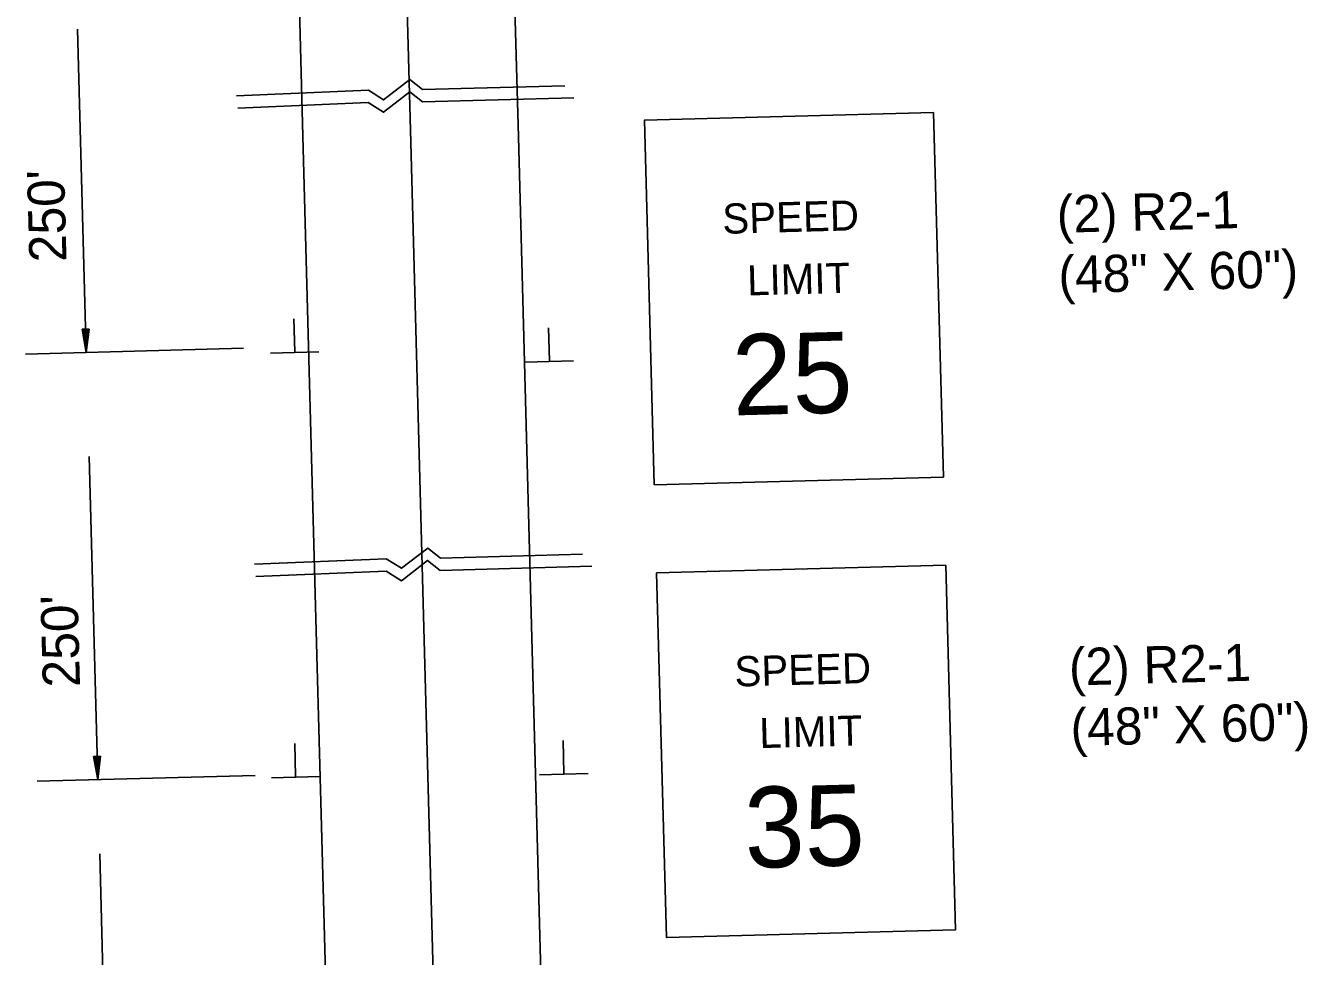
# Model space of a CAD drawing. Extents: x 1926836 to 1933254, y 596317 to 604524.
# Drawn here: x 1930973.1 to 1931180.1, y 596501.1 to 596651.4 of the extents above; entities that cross this region are included whole.
import ezdxf

# ---------------------------------------------------------------- set-up
doc = ezdxf.new("R2010")
doc.units = 0
doc.layers.add('Default', color=7, linetype='Continuous')

msp = doc.modelspace()

# ---------------------------------------------------------------- linework, layer by layer
at = {"layer": 'Default'}
for p, q in [((1931017.97, 596631.53), (1931016.3, 596693.48)), ((1931035.33, 596632.46), (1931033.69, 596693.61)), ((1931052.7, 596633.38), (1931051.08, 596693.74)), ((1930982.92, 596598.6), (1930981.52, 596650.77)), ((1931054.71, 596558.55), (1931052.7, 596633.38)), ((1931019.95, 596557.62), (1931017.97, 596631.53)), ((1931037.33, 596558.09), (1931035.33, 596632.46)), ((1931016.59, 596598.7), (1931016.45, 596604.04)), ((1930983.38, 596602.36), (1930982.26, 596602.33)), ((1930982.26, 596602.33), (1930982.92, 596598.6)), ((1930982.35, 596602.33), (1930982.9, 596599.22)), ((1930982.44, 596602.33), (1930982.88, 596599.87)), ((1930982.54, 596602.34), (1930982.87, 596600.49)), ((1930982.63, 596602.34), (1930982.85, 596601.13)), ((1930982.73, 596602.34), (1930982.83, 596601.75)), ((1930982.91, 596602.35), (1930982.83, 596601.75)), ((1930983, 596602.35), (1930982.85, 596601.13)), ((1930983.1, 596602.35), (1930982.87, 596600.49)), ((1930983.19, 596602.35), (1930982.88, 596599.87)), ((1930983.29, 596602.36), (1930982.9, 596599.22)), ((1930983.38, 596602.36), (1930982.92, 596598.6)), ((1931057.7, 596597.23), (1931057.56, 596602.57)), ((1930973.13, 596598.33), (1931008.33, 596599.28)), ((1931020.48, 596598.69), (1931012.66, 596598.48)), ((1931061.59, 596597.22), (1931053.77, 596597.01)), ((1930984.77, 596529.62), (1930983.37, 596581.79)), ((1931056.56, 596489.57), (1931054.71, 596558.55)), ((1931021.8, 596488.64), (1931019.95, 596557.62)), ((1931039.18, 596489.11), (1931037.33, 596558.09)), ((1931060.05, 596530.6), (1931059.91, 596535.94)), ((1931016.73, 596530.12), (1931016.59, 596535.45)), ((1930985.23, 596533.38), (1930984.11, 596533.35)), ((1930984.11, 596533.35), (1930984.77, 596529.62)), ((1930984.2, 596533.35), (1930984.75, 596530.24)), ((1930984.3, 596533.35), (1930984.74, 596530.89)), ((1930984.39, 596533.36), (1930984.72, 596531.51)), ((1930984.49, 596533.36), (1930984.7, 596532.15)), ((1930984.58, 596533.36), (1930984.68, 596532.77)), ((1930984.76, 596533.37), (1930984.68, 596532.77)), ((1930984.85, 596533.37), (1930984.7, 596532.15)), ((1930984.95, 596533.37), (1930984.72, 596531.51)), ((1930985.04, 596533.37), (1930984.74, 596530.89)), ((1930985.14, 596533.38), (1930984.75, 596530.24)), ((1930985.23, 596533.38), (1930984.77, 596529.62)), ((1930974.98, 596529.35), (1931010.18, 596530.3)), ((1931020.63, 596530.11), (1931012.81, 596529.9)), ((1931063.95, 596530.59), (1931056.13, 596530.38)), ((1930986.49, 596465.48), (1930985.09, 596517.65))]:
    msp.add_line(p, q, dxfattribs=at)
for points in [[(1931007.18, 596640.03), (1931028.47, 596640.92), (1931030.93, 596639.37), (1931035.17, 596642.65), (1931037.22, 596641.03), (1931060.17, 596641.65)], [(1931007.42, 596638.04), (1931028.44, 596638.93), (1931030.9, 596637.37), (1931035.14, 596640.65), (1931037.19, 596639.03), (1931061.63, 596639.69)], [(1931010.08, 596564.4), (1931031.37, 596565.29), (1931033.83, 596563.74), (1931038.07, 596567.01), (1931040.11, 596565.4), (1931063.07, 596566.02)], [(1931010.32, 596562.41), (1931031.34, 596563.3), (1931033.8, 596561.74), (1931038.04, 596565.02), (1931040.08, 596563.4), (1931064.53, 596564.06)]]:
    msp.add_lwpolyline(points, dxfattribs=at)
for points in [[(1931119.73, 596637.32), (1931121.31, 596578.47), (1931074.62, 596577.22), (1931073.04, 596636.07)], [(1931121.7, 596564.24), (1931123.28, 596505.39), (1931076.59, 596504.13), (1931075.01, 596562.98)]]:
    msp.add_lwpolyline(points, close=True, dxfattribs=at)

# ---------------------------------------------------------------- texts
for s, height, rotation, p in [("250'", 6, 91.5377, (1930979.74, 596613.25)), ('(2) R2-1', 6, 1.5377, (1931139.7, 596617.89)), ('SPEED', 4.865, 1.5377, (1931085.69, 596617.73)), ('(48" X 60")', 6, 1.5377, (1931139.97, 596608.11)), ('LIMIT', 4.865, 1.5377, (1931089.69, 596607.78)), ('25', 13.039, 1.5377, (1931087.38, 596588.41)), ("250'", 6, 91.5377, (1930981.92, 596544.59)), ('SPEED', 4.865, 1.5377, (1931087.65, 596544.64)), ('(2) R2-1', 6, 1.5377, (1931141.67, 596544.8)), ('(48" X 60")', 6, 1.5377, (1931141.93, 596535.03)), ('LIMIT', 4.865, 1.5377, (1931091.65, 596534.7)), ('35', 13.039, 1.5377, (1931089.35, 596515.33))]:
    msp.add_text(s, height=height, rotation=rotation, dxfattribs=at).set_placement(p)

doc.saveas('drawing.dxf')
